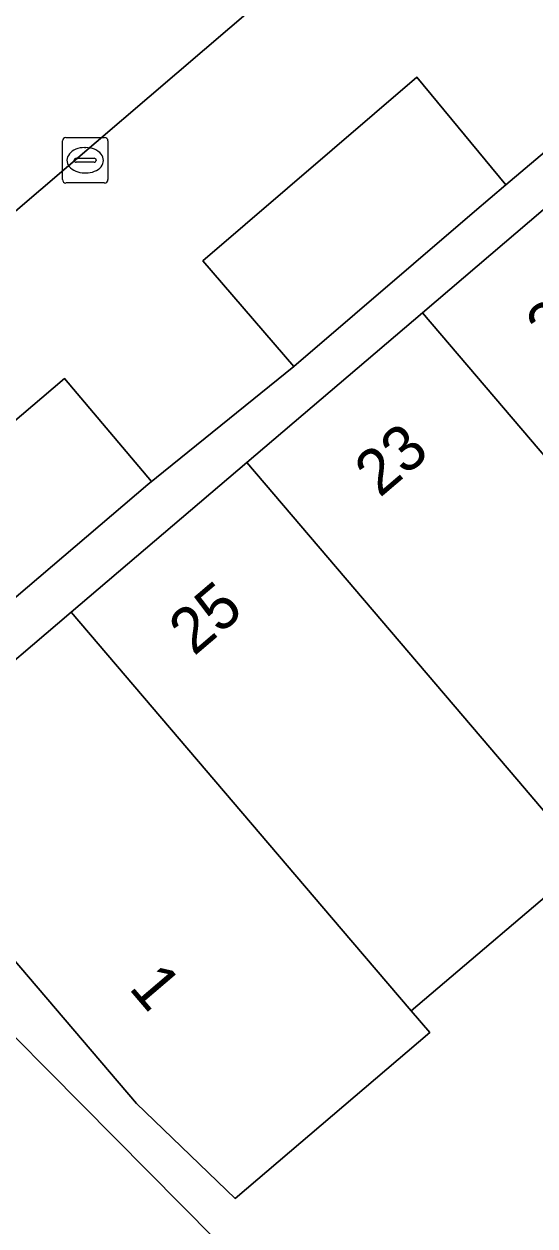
# Model space of a CAD drawing. Extents: x 160377 to 161131, y 383938 to 384853.
# Drawn here: x 160702.02 to 160713.26, y 384618.43 to 384644.89 of the extents above; entities that cross this region are included whole.
import ezdxf

# ---------------------------------------------------------------- set-up
doc = ezdxf.new("R2010")
doc.units = 0
for name, color, linetype in [('IMGEO_Erf', 7, 'Continuous'), ('IMGEO_Groenvoorziening', 7, 'Continuous'), ('IMGEO_Kolk', 7, 'Continuous'), ('IMGEO_Pand', 7, 'Continuous'), ('IMGEO_Pand_nummerreeks', 7, 'Continuous'), ('IMGEO_Voetgangersgebied_open', 7, 'Continuous')]:
    doc.layers.add(name, color=color, linetype=linetype)

msp = doc.modelspace()

# ---------------------------------------------------------------- linework, layer by layer
at = {"layer": 'IMGEO_Erf'}
for points in [[(160715.683, 384643.941), (160712.616, 384641.352), (160711.93, 384640.763), (160707.952, 384637.348), (160704.741, 384634.75), (160697.843, 384628.87), (160696.648, 384627.802), (160696.715, 384627.735), (160704.012, 384620.371), (160714.28, 384609.995)], [(160714.4, 384626.456), (160710.537, 384623.165), (160710.942, 384622.689), (160706.66, 384619.033), (160704.491, 384621.131), (160698.547, 384628.1), (160703.054, 384631.943), (160706.918, 384635.239), (160710.78, 384638.533), (160714.642, 384641.826)]]:
    msp.add_lwpolyline(points, dxfattribs=at)
at = {"layer": 'IMGEO_Groenvoorziening'}
msp.add_lwpolyline([(160697.903, 384638.25), (160698.397, 384637.84), (160701.212, 384640.247), (160707.15, 384645.327)], dxfattribs=at)
for points in [[(160712.616, 384641.352), (160710.66, 384643.716), (160705.952, 384639.673), (160707.952, 384637.348), (160711.93, 384640.763)], [(160704.741, 384634.75), (160704.821, 384634.818), (160702.91, 384637.088), (160694.536, 384629.95), (160696.648, 384627.802), (160697.843, 384628.87)]]:
    msp.add_lwpolyline(points, close=True, dxfattribs=at)
at = {"layer": 'IMGEO_Kolk'}
for p, q in [((160702.862, 384641.463), (160702.862, 384642.315)), ((160702.937, 384642.389), (160703.789, 384642.389)), ((160703.35, 384642.169), (160703.375, 384642.169)), ((160703.863, 384642.315), (160703.863, 384641.463)), ((160703.121, 384641.883), (160703.121, 384641.895)), ((160703.164, 384641.932), (160703.562, 384641.932)), ((160703.605, 384641.895), (160703.605, 384641.883)), ((160703.559, 384641.846), (160703.161, 384641.846)), ((160703.789, 384641.389), (160702.937, 384641.389)), ((160703.373, 384641.609), (160703.348, 384641.609))]:
    msp.add_line(p, q, dxfattribs=at)
for points in [[(160702.862, 384641.463), (160702.862, 384642.315)], [(160702.937, 384642.389), (160703.789, 384642.389)], [(160703.863, 384642.315), (160703.863, 384641.463)], [(160703.789, 384641.389), (160702.937, 384641.389)]]:
    msp.add_lwpolyline(points, dxfattribs=at)
for centre, radius, start, end in [((160702.939, 384642.313), 0.0765, 91.552, 178.448), ((160702.939, 384642.313), 0.0765, 91.552, 178.448), ((160703.787, 384642.313), 0.0765, 1.552, 88.448), ((160703.787, 384642.313), 0.0765, 1.552, 88.448), ((160703.161, 384641.892), 0.0403, 85.8775, 175.7526), ((160703.566, 384641.894), 0.0386, 1.7309, 96.639), ((160703.158, 384641.882), 0.0366, 178.938, 274.7102), ((160703.562, 384641.889), 0.043, 264.8664, 352.4533), ((160702.939, 384641.465), 0.0765, 181.552, 268.448), ((160702.939, 384641.465), 0.0765, 181.552, 268.448), ((160703.787, 384641.465), 0.0765, 271.552, 358.448), ((160703.787, 384641.465), 0.0765, 271.552, 358.448)]:
    msp.add_arc(centre, radius, start, end, dxfattribs=at)
for centre, major_axis, ratio, start_param, end_param in [((160703.349, 384641.889), (-0.387, 0.002), 0.722429, 4.712389, 7.853982), ((160703.374, 384641.889), (-0.39, 0.002), 0.717154, 1.570796, 4.712389)]:
    msp.add_ellipse(centre, major_axis=major_axis, ratio=ratio, start_param=start_param, end_param=end_param, dxfattribs=at)
at = {"layer": 'IMGEO_Pand'}
for points in [[(160714.642, 384641.826), (160710.78, 384638.533), (160716.721, 384631.559), (160718.264, 384629.748), (160722.127, 384633.04), (160720.588, 384634.847)], [(160710.78, 384638.533), (160706.918, 384635.239), (160712.86, 384628.264), (160714.4, 384626.456), (160718.264, 384629.748), (160716.721, 384631.559)], [(160706.918, 384635.239), (160703.054, 384631.943), (160708.996, 384624.972), (160710.537, 384623.165), (160714.4, 384626.456), (160712.86, 384628.264)], [(160703.054, 384631.943), (160698.547, 384628.1), (160704.491, 384621.131), (160706.66, 384619.033), (160710.942, 384622.689), (160710.537, 384623.165), (160708.996, 384624.972)]]:
    msp.add_lwpolyline(points, close=True, dxfattribs=at)
at = {"layer": 'IMGEO_Voetgangersgebied_open'}
for points in [[(160710.66, 384643.716), (160712.616, 384641.352), (160715.683, 384643.941), (160713.716, 384646.315), (160718.375, 384650.288), (160720.379, 384647.933), (160723.454, 384650.553), (160721.435, 384652.883), (160726.14, 384656.932), (160728.177, 384654.568), (160731.208, 384657.183), (160729.194, 384659.54), (160730.884, 384660.985), (160736.564, 384665.84), (160738.544, 384663.515), (160738.585, 384663.466), (160738.611, 384663.488), (160741.8, 384666.319), (160734.733, 384674.665)], [(160703.235, 384654.813), (160686.913, 384640.854), (160683.437, 384638.06), (160688.26, 384633.172), (160688.847, 384632.577), (160689.296, 384632.117), (160689.815, 384631.58), (160686.54, 384628.777), (160687.061, 384628.162), (160666.311, 384610.443), (160669.413, 384608.444), (160680.377, 384617.831), (160686.599, 384623.159), (160692.615, 384628.309), (160694.536, 384629.95), (160702.91, 384637.088), (160704.821, 384634.818), (160704.741, 384634.75), (160707.952, 384637.348), (160705.952, 384639.673), (160710.66, 384643.716)], [(160707.002, 384653.367), (160712.463, 384649.871), (160707.15, 384645.327), (160701.212, 384640.247)], [(160755.906, 384542.287), (160755.616, 384543.763), (160752.301, 384560.653), (160749.625, 384574.277), (160715.318, 384608.946), (160714.28, 384609.995), (160704.012, 384620.371), (160696.715, 384627.735), (160696.648, 384627.802), (160694.536, 384629.95), (160692.615, 384628.309), (160698.73, 384622.125), (160700.47, 384620.379)]]:
    msp.add_lwpolyline(points, dxfattribs=at)

# ---------------------------------------------------------------- texts
at = {"layer": 'IMGEO_Pand_nummerreeks'}
for s, rotation, p in [('21', 40.4565, (160713.612, 384637.663)), ('23', 40.4565, (160709.842, 384634.448)), ('25', 40.4565, (160705.755, 384630.962)), ('1', 310.4621, (160704.301, 384623.664))]:
    msp.add_text(s, height=1, rotation=rotation, dxfattribs=at).set_placement(p)

doc.saveas('drawing.dxf')
